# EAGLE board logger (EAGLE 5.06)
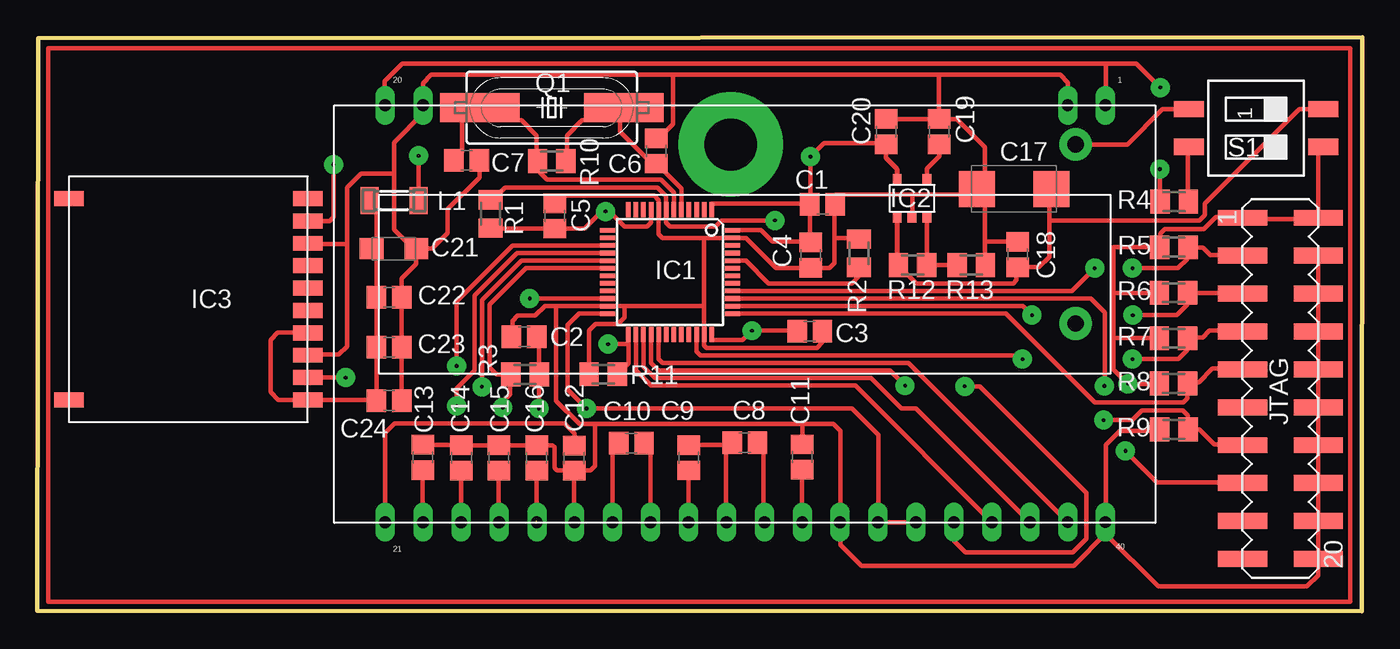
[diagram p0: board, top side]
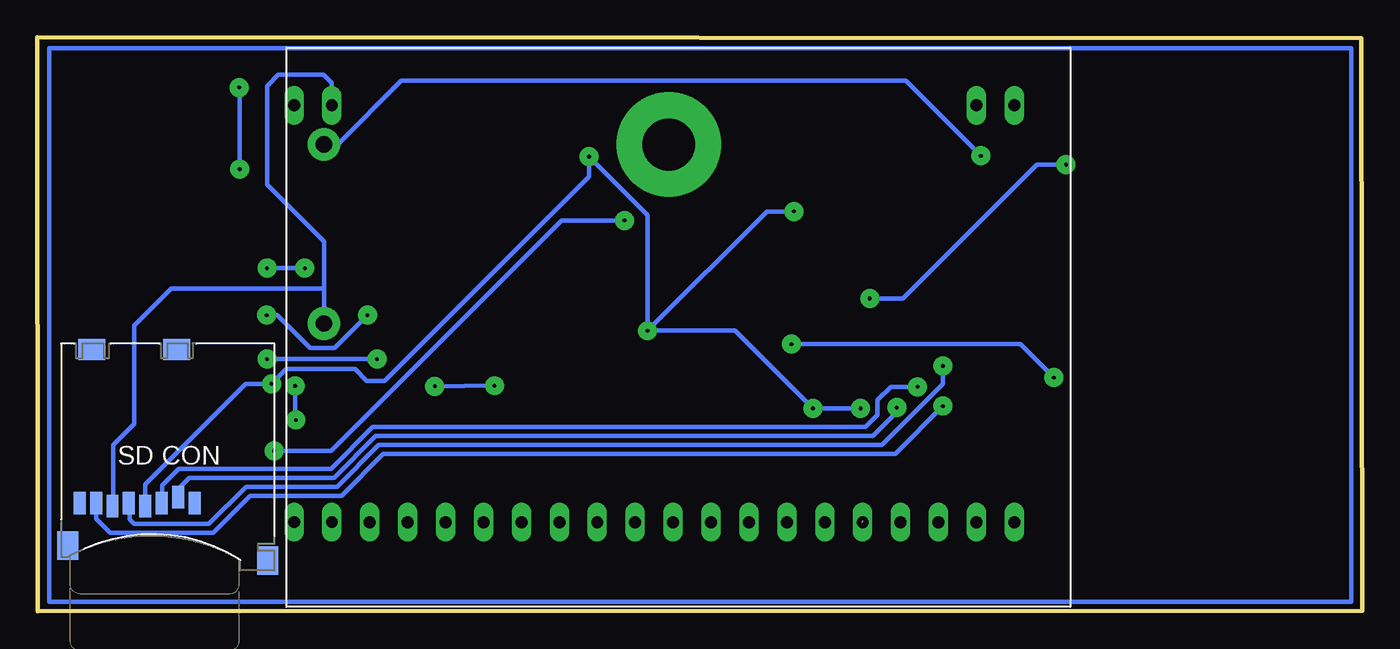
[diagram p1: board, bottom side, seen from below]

Size 88.76 x 38.47 mm. Coordinates in mm from the lower left corner, seen from the top.
Outline: 0,0.03 88.73,0 88.76,38.47 0.05,38.42 0,0.03
Copper layers (1*16): Top 0.035mm / dielectric 1.5mm / Bottom 0.035mm
Design rules "default": minimum track width 10mil, minimum drill 24mil, track to track 8mil, track to pad 8mil, pad to pad 8mil, via to via 8mil, smd to smd 8mil, copper to edge 40mil, drill to drill 8mil, minimum pad ring 10mil, minimum via ring 8mil, stop-mask expansion 4mil, vias tented up to drill 0mil, thermal gap 10mil

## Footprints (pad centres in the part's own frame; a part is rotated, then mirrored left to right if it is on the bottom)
C0805 = smd 1.3 x 1.5: 1 -0.85,0; 2 0.85,0
SMC_C = smd 2.4 x 2.4: + -2.5,0; - 2.5,0
SMC_A = smd 1.6 x 1.4: + -1.5,0; - 1.5,0
SM-1206 = smd 1.2 x 1.8: 1 -1.65,0; 2 1.65,0
HC49UP = smd 5.334 x 1.93: 1 -4.826,0; 2 4.826,0
M0805 = smd 1.3 x 1.6: 1 -0.95,0; 2 0.95,0
SMS-002 = smd 1.092 x 2.007: 1 -1.27,-4.496; 2 1.27,-4.496; 3 1.27,4.496; 4 -1.27,4.496
MA10-2 = smd 1.067 x 3.302: 1 -11.43,-2.54; 2 -11.43,2.54; 3 -8.89,-2.54; 4 -8.89,2.54; 5 -6.35,-2.54; 6 -6.35,2.54; 7 -3.81,-2.54; 8 -3.81,2.54; 9 -1.27,-2.54; 10 -1.27,2.54; 11 1.27,-2.54; 12 1.27,2.54; 13 3.81,-2.54; 14 3.81,2.54; 15 6.35,-2.54; 16 6.35,2.54; 17 8.89,-2.54; 18 8.89,2.54; 19 11.43,-2.54; 20 11.43,2.54
TQFP48 = smd 1.016 x 0.305: 1 -4.191,2.794; 2 -4.191,2.286; 3 -4.191,1.778; 4 -4.191,1.27; 5 -4.191,0.762; 6 -4.191,0.254; 7 -4.191,-0.254; 8 -4.191,-0.762; 9 -4.191,-1.27; 10 -4.191,-1.778; 11 -4.191,-2.286; 12 -4.191,-2.794; 25 4.191,-2.794; 26 4.191,-2.286; 27 4.191,-1.778; 28 4.191,-1.27; 29 4.191,-0.762; 30 4.191,-0.254; 31 4.191,0.254; 32 4.191,0.762; 33 4.191,1.27; 34 4.191,1.778; 35 4.191,2.286; 36 4.191,2.794 | smd 0.305 x 1.016: 13 -2.794,-4.191; 14 -2.286,-4.191; 15 -1.778,-4.191; 16 -1.27,-4.191; 17 -0.762,-4.191; 18 -0.254,-4.191; 19 0.254,-4.191; 20 0.762,-4.191; 21 1.27,-4.191; 22 1.778,-4.191; 23 2.286,-4.191; 24 2.794,-4.191; 37 2.794,4.191; 38 2.286,4.191; 39 1.778,4.191; 40 1.27,4.191; 41 0.762,4.191; 42 0.254,4.191; 43 -0.254,4.191; 44 -0.762,4.191; 45 -1.27,4.191; 46 -1.778,4.191; 47 -2.286,4.191; 48 -2.794,4.191
MICROSD = smd 0.8 x 1.5: 1 -1.94,2.7; 2 -0.84,2.3; 3 0.26,2.7; 4 1.36,2.9; 5 2.46,2.7; 6 3.56,2.9; 7 4.66,2.7; 8 5.76,2.7 | smd 1.4 x 1.9: NC -6.85,6.55; NC3 6.55,5.55 | smd 1.8 x 1.4: NC1 -0.75,-7.6; NC2 4.95,-7.6
GPS_FGMMOPA6B = smd 2 x 1: 1 -2.5,7.5; 2 -2.5,6; 3 -2.5,4.5; 4 -2.5,3; 5 -2.5,1.5; 6 -2.5,0; 7 -2.5,-1.5; 8 -2.5,-3; 9 -2.5,-4.5; 10 -2.5,-6; P$11 13.5,7.5; P$12 13.5,-6
3V110R = drill 1.1 pad 2.184 round: MINUS -2.5,-19; PLUS -2.5,-31 | drill 3.5 pad 7 round: P$1 -25.6,-30.99
LP3985 = smd 0.65 x 0.6: 1 -1.2,0.53; 2 -1.2,-0.47; 3 -1.2,-1.47; 4 1.4,-1.47; 5 1.4,0.53
E_DOG-M_DISPLAY = drill 0.8 long: 1 3.334,0; 2 5.874,0; 19 49.054,0; 20 51.594,0; 21 51.594,27.94; 22 49.054,27.94; 23 46.514,27.94; 24 43.974,27.94; 25 41.434,27.94; 26 38.894,27.94; 27 36.354,27.94; 28 33.814,27.94; 29 31.274,27.94; 30 28.734,27.94; 31 26.194,27.94; 32 23.654,27.94; 33 21.114,27.94; 34 18.574,27.94; 35 16.034,27.94; 36 13.494,27.94; 37 10.954,27.94; 38 8.414,27.94; 39 5.874,27.94; 40 3.334,27.94

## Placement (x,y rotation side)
C1  100nF  [C0805]  52.61,27.28 180 top
C2  100nF  [C0805]  32.62,18.41 0 top
C3  100nF  [C0805]  51.75,18.78 180 top
C4  100nF  [C0805]  51.82,23.87 270 top
C5  100nF  [C0805]  34.66,26.5 90 top
C6  22pF  [C0805]  41.47,30.86 270 top
C7  22pF  [C0805]  28.76,30.21 180 top
C8  1uF  [C0805]  47.4,11.31 180 top
C9  1uF  [C0805]  43.63,10.29 270 top
C10  1uF  [C0805]  39.8,11.26 0 top
C11  1uF  [C0805]  51.24,10.34 90 top
C12  1uF  [C0805]  35.96,10.27 270 top
C13  1uF  [C0805]  25.82,10.31 90 top
C14  1uF  [C0805]  28.42,10.29 90 top
C15  1uF  [C0805]  30.91,10.29 90 top
C16  1uF  [C0805]  33.45,10.29 90 top
C17  100uF  [SMC_C]  65.44,28.31 180 top
C18  1uF  [C0805]  65.68,23.92 90 top
C19  10nF  [C0805]  60.42,32.14 90 top
C20  1uF  [C0805]  56.87,32.14 90 top
C21  10uF  [SMC_A]  23.89,24.31 0 top
C22  1uF  [C0805]  23.57,21.05 0 top
C23  100nF  [C0805]  23.57,17.69 0 top
C24  10nF  [C0805]  23.57,14.13 0 top
L1  [SM-1206]  23.91,27.54 180 top
Q1  8.00MHz  [HC49UP]  34.47,33.76 0 top
R1  10k  [M0805]  30.36,26.64 270 top
R2  10k  [M0805]  55.06,24 270 top
R3  4k7  [M0805]  32.67,15.88 0 top
R4  100  [M0805]  76.16,27.46 0 top
R5  10k  [M0805]  76.15,24.4 180 top
R6  10k  [M0805]  76.12,21.35 180 top
R7  10k  [M0805]  76.12,18.3 180 top
R8  10k  [M0805]  76.12,15.28 180 top
R9  10k  [M0805]  76.14,12.2 0 top
R10  1M  [M0805]  34.46,30.18 0 top
R11  10k  [M0805]  37.92,15.89 180 top
R12  14,3k  [M0805]  58.64,23.2 180 top
R13  10k  [M0805]  62.56,23.2 180 top
S1  SWS002  [SMS-002]  81.65,32.39 270 top
SV1  [MA10-2]  83.28,14.94 270 top
U$1  STM32  [TQFP48]  42.39,22.74 270 top
U$2  MICROSD  [MICROSD]  80.17,9.95 180 bottom
U$3  GPS_FGMMOPA6B  [GPS_FGMMOPA6B]  15.62,21.66 180 top
U$4  3V110R  [3V110R]  72.06,0.29 180 bottom
U$5  LP3985  [LP3985]  58.14,27.57 90 top
U$6  EA_DOG-M_DISPLAY  [E_DOG-M_DISPLAY]  74.9,33.92 180 top

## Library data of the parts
C1-C24 R1-R13 = rcl
L1 = inductor-neosid
Q1 = crystal
S1 = smd-special
SV1 = goldpiny_smd
U$1 = stm32
U$2 = microsd
U$3 = GPS_FGMMOPA6B
U$4 = battery_pack
U$5 = lp3985
U$6 = display_ea_dogm132

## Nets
+3V3: C1.2 C2.2 C3.2 C4.1 C5.1 C20.1 R1.2 R3.2 R5.2 R6.2 R7.2 R8.2 S1.3 SV1.1 SV1.2 U$1.1 U$1.9 U$1.24 U$1.36 U$1.48 U$2.4 U$5.5 U$6.34 U$6.35
BOOT_0: R2.2 U$1.44
GND: C1.1 C2.1 C3.1 C4.2 C5.2 C6.1 C7.1 C11.2 C12.2 C13.2 C14.2 C15.2 C16.2 C17.- C18.2 C19.2 C20.2 C21.- C22.2 C23.2 C24.2 R2.1 R9.1 R11.2 R13.1 SV1.4 SV1.6 SV1.8 SV1.10 SV1.12 SV1.14 SV1.16 SV1.18 SV1.20 U$1.8 U$1.23 U$1.35 U$1.47 U$2.6 U$3.3 U$3.8 U$4.MINUS U$5.2 U$6.2 U$6.19 U$6.26 U$6.33 U$6.40
GPS_DATA: U$1.22 U$3.9
GPS_ENABLE: C21.+ C22.1 C23.1 C24.1 L1.2 U$3.1 U$3.4
JTAG_RST: R1.1 SV1.15 U$1.7
JTAG_TCK: R8.1 SV1.9 U$1.37
JTAG_TDI: R6.1 SV1.5 U$1.38
JTAG_TMS: R7.1 SV1.7 U$1.34
JTAG_TRST: R5.1 SV1.3 U$1.40
KTAG_TDO: R9.2 SV1.13 U$1.39
LCD_A0: U$1.27 U$6.38
LCD_RST: U$1.29 U$6.39
LCD_SCL: U$1.26 U$6.37
LCD_SI: U$1.28 U$6.36
N$2: C19.1 U$5.4
N$3: C7.2 Q1.1 R10.1 U$1.6
N$4: C6.2 Q1.2 R10.2 U$1.5
N$6: L1.1 S1.1 U$4.PLUS
N$7: R12.1 R13.2 U$5.3
N$9: R11.1 U$1.25 U$3.2
N$10: R4.1 U$6.1 U$6.20
N$12: C8.1 U$6.31
N$13: C14.1 U$6.23
N$14: C13.1 U$6.22
N$15: C12.1 U$6.21
N$16: C15.1 U$6.24
N$17: C16.1 U$6.25
N$18: C10.1 U$6.27
N$19: C8.2 C9.1 U$6.30
N$20: C9.2 U$6.29
N$21: C10.2 U$6.28
N$22: C11.1 U$6.32
N$28: R4.2 S1.2
N$36: C17.+ C18.1 R12.2 S1.4 U$5.1
SD_CARD_CLK: U$1.15 U$2.5
SD_CARD_CS: R3.1 U$1.18 U$2.2
SD_CARD_DI: U$1.17 U$2.3
SD_CARD_DO: U$1.16 U$2.7

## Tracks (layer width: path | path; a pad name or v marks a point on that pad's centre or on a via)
+3V3  (via drill 0.25 pad 1.27)
  Top 0.305: S1.3 85.42,31.08 | 75.2,24.32 R5.2 | R5.2 75.18,24.42 72.11,24.42 | 72.11,23.86 72.11,23.94 | R6.2 72.11,21.35 | 75.23,15.25 75.2,15.28 R8.2 75.15,15.26 | 75.15,15.26 75.15,15.12 | 75.15,18.29 R7.2 75.15,18.32 72.11,18.32 | 75.15,15.26 75.14,15.25 v73.07,15.25 | v73.07,15.25 72.11,16.21 72.11,16.39 | 72.11,16.39 72.11,18.32 | U$1.36 45.18,18.17 47.24,18.17 v47.87,18.81 50.87,18.81 | 50.77,18.42 50.77,18.68 50.8,18.68 C3.2 50.87,18.81 | 50.52,13.6 v36.8,13.6 35.53,14.87 35.53,19.19 36.29,19.95 U$1.24 | 50.52,13.6 50.77,13.6 | 51.81,26.68 51.72,26.68 C1.2 | 58.9,5.98 U$6.35 U$6.34 56.36,6.01 56.36,11.82 54.58,13.6 50.52,13.6 | 58.9,5.98 | 80.82,26.3 SV1.1 | 80.82,26.3 80.15,26.3 80.02,26.43 78.96,26.43 78.16,25.63 75.54,25.63 75.23,25.32 75.23,24.43 R5.2 | 85.19,26.3 85.06,26.43 | 80.82,26.3 85.19,26.3 | 85.82,26.3 SV1.2 | 85.82,31.12 S1.3 | 85.19,26.3 85.82,26.3 | S1.3 85.9,30.87 85.82,30.87 85.82,26.3 | 72.11,24.42 72.11,23.86 | 72.11,23.86 72.11,21.35 | 72.11,18.32 72.11,21.35 | C1.2 51.71,26.67 51.76,26.61 51.76,24.77 | U$1.9 41.12,26.04 40.86,25.79 39.34,25.79 38.32,26.81 v38.07,26.81 37.82,26.81 36.66,25.65 C5.1 30.37,25.65 30.34,25.69 R1.2 | 50.87,18.81 v47.88,18.81 | v33.6,13.6 33.6,15.6 R3.2 33.62,18.41 C2.2 | C1.2 51.73,27.31 45.18,27.31 U$1.1 | U$1.48 48.48,25.54 49.25,24.77 51.76,24.77 | 51.76,24.77 C4.1 | 56.87,31.12 C20.1 | U$5.5 57.61,29.42 | U$5.5 57.61,29.67 56.87,30.41 56.87,31.12 | 56.87,31.12 56.87,31.38 52.8,31.38 | C1.2 51.79,27.3 51.79,30.36 v51.79,30.47 52.7,31.38 52.8,31.38 | U$5.5 57.63,28.99 57.63,29.6 56.87,30.36 56.87,31.12 | 56.87,31.12 56.61,31.38 52.8,31.38 | 72.11,16.39 72.11,24.42
  Top 0.305: 72.11,16.39 72.11,16.22 v73.07,15.25
  Bottom 0.305: v33.6,13.6 v36.8,13.6 42.01,18.81 v47.87,18.81 | v47.87,18.81 47.85,18.81 | v47.87,18.81 47.03,18.81 | v38.07,26.81 39.87,26.81 v47.87,18.81 | v47.87,18.81 47.87,26.55 v51.79,30.47 51.79,29.14 65.48,15.45 66.68,15.45 67.48,16.25 72.07,16.25 v73.07,15.25 74.78,15.25 81.53,8.51 U$2.4
BOOT_0
  Top 0.305: U$1.44 47.47,23.5 48.99,21.98 54.58,21.98 55.09,22.49 55.09,23.02 R2.2
GND
  Top 0.305: C12.2 35.96,9.34 35.96,6.49 | 35.96,6.49 35.96,6.07 | C13.2 | C13.2 28.42,11.16 C14.2 30.85,11.14 30.86,11.13 30.86,11.14 C15.2 33.34,11.14 33.35,11.13 33.35,11.14 C16.2 34.51,11.14 34.64,11.01 34.64,9.61 34.82,9.43 35.94,9.43 C12.2 | 35.58,9.41 35.59,9.42 C12.2 | 51.22,11.21 51.2,11.21 | 51.22,11.21 C11.2 | C12.2 35.96,9.46 36.06,9.46 37.05,9.46 37.36,9.76 37.36,12.56 | U$3.8 18.17,24.62 20.13,24.62 | 20.13,24.62 20.24,24.62 | U$3.3 18.11,17.18 18.11,17.2 20.18,17.2 20.74,17.76 20.74,24.62 | 25.88,33.97 25.88,33.92 U$6.19 | 20.74,24.62 20.13,24.62 | 34.77,20.46 U$1.23 | C1.1 53.41,26.65 53.41,25.03 | 53.36,26.7 53.36,26.69 C1.1 | 39.34,20.46 34.77,20.46 | 44.67,20.46 39.34,20.46 | 44.93,25.03 44.67,25.03 44.67,20.46 | 44.93,25.03 U$1.47 47.47,25.03 49.47,23.02 C4.2 53.08,23.02 53.41,23.35 53.41,25.03 | 41.63,27.06 U$1.8 | C3.1 52.6,18.04 52.22,17.66 44.83,17.66 44.67,17.81 U$1.35 44.67,20.46 | 41.63,27.06 41.63,25.28 41.88,25.03 44.93,25.03 | 69.06,34.02 69.06,33.92 U$6.2 69.06,33.95 69.06,35.44 68.55,35.95 60.41,35.95 | 35.96,6.49 36.04,6.49 36.04,5.98 U$6.26 | 85.82,4.2 SV1.20 | 85.82,4.2 SV1.18 SV1.16 SV1.14 SV1.12 SV1.10 SV1.8 SV1.6 | SV1.6 85.82,21.47 | 85.82,24.01 SV1.4 SV1.6 | 41.63,27.06 41.63,27.57 41.34,27.85 34.97,27.85 34.66,27.54 C5.2 | C24.2 C23.2 | C23.2 | C23.2 C22.2 24.42,22.29 25.39,23.26 C21.- | C21.- 25.67,24.03 25.67,23.8 23.89,25.58 23.89,29.25 | 34.77,20.46 34.01,20.46 33.36,19.81 32.18,19.81 31.84,19.47 31.84,18.48 C2.1 | 37.36,12.56 36.32,12.56 34.77,14.11 34.77,20.46 | 39.34,20.46 39.34,19.69 38.9,19.25 37.38,19.25 36.97,18.83 R11.2 | U$6.19 25.85,33.38 23.89,31.42 23.89,29.25
  Top 0.305: 41.61,31.81 C6.1 41.81,32.15 42.08,32.15 42.58,32.65 42.58,35.95 43.15,35.95 | 37.36,12.56 51.28,12.56 | 51.22,11.21 51.28,11.27 51.28,12.56 | 85.82,4.2 85.82,2.42 85.06,1.66 75.09,1.66 71.57,5.18 | R9.1 75.07,12.07 72.51,12.07 71.6,11.16 71.6,5.5 71.57,5.47 | 51.28,12.56 53.33,12.56 53.82,12.07 53.82,6.01 U$6.33 53.82,5.95 53.82,4.45 55.22,3.05 69.43,3.05 71.57,5.18 | R2.1 54.98,25.03 53.41,25.03 | 71.57,5.18 71.57,5.47 | 71.57,5.47 U$6.40 | U$6.19 25.85,35.41 26.39,35.95 43.15,35.95 | 43.15,35.95 60.41,35.95 | 53.46,27.92 C1.1 | 59.91,32.99 C19.2 | U$5.2 58.64,26.41 58.64,27.92 | 53.46,27.92 58.29,27.92 | 59.91,32.99 60.33,32.99 arc-90 60.42,32.9 60.41,32.9 60.41,35.95 | 59.91,32.99 C20.2 | 58.64,27.92 53.46,27.92 | 58.64,27.92 62.55,27.92 C17.- 62.94,27.82 63.47,27.82 63.47,24.77 | R13.1 63.47,23.2 63.47,24.77 | C18.2 63.47,24.77 | 63.47,24.77 63.47,31.12 61.6,32.99 59.91,32.99 | C7.1 29.61,29.08 27.48,26.95 27.48,25.35 26.44,24.31 C21.- | 20.74,24.62 20.74,28.41 21.68,29.35 23.79,29.35 23.89,29.25
  Bottom 0.305: U$6.2 69.03,34.39 69.06,34.43 69.06,35.44 69.57,35.95 72.61,35.95 73.38,35.19 73.38,28.58 69.56,24.77 69.56,21.65 | 69.56,21.65 U$4.MINUS | U$2.6 83.68,7.09 83.68,11.15 82.28,12.55 82.28,19.15 79.78,21.65 69.56,21.65
GPS_DATA  (via drill 0.25 pad 1.27)
  Top 0.305: 18.15,26.14 U$3.9 18.14,26.15 19.58,26.15 19.84,26.41 v19.84,29.94 | v32.99,20.96 U$1.22
  Bottom 0.305: v32.99,20.96 30.77,20.96 21.79,29.94 v19.84,29.94
GPS_ENABLE
  Top 0.305: U$3.4 18.12,18.67 16.1,18.67 15.62,18.19 15.62,14.71 16.15,14.18 18.13,14.18 18.13,14.17 U$3.1 18.14,14.15 22.69,14.15 C24.1 C23.1 22.72,21.35 C22.1 22.72,23.98 C21.+ 22.74,24.65 22.74,27.07 22.27,27.54 L1.2
JTAG_RST  (via drill 0.25 pad 1.27)
  Top 0.305: 80.49,8.52 80.15,8.52 80.02,8.65 75,8.65 v72.9,10.75 | 80.49,8.52 80.67,8.52 SV1.15 | 80.49,8.52 81.5,8.52 | R1.1 30.76,28 30.95,28 31.35,28.4 41.56,28.4 42.13,27.82 U$1.7 42.13,26.04 42.39,25.79 45.44,25.79 45.84,26.2 v49.42,26.2
  Bottom 0.305: v49.42,26.2 53.64,26.2 69.09,10.75 v72.9,10.75
JTAG_TCK
  Top 0.305: R8.1 77.14,15.35 77.82,15.35 78.73,16.27 80.02,16.27 80.15,16.14 80.82,16.14 | R8.1 77.08,15.27 | R8.1 77.07,15.16 77.06,15.15 77.06,14.28 76.78,14 70.84,14 64.89,19.95 U$1.37 | 80.82,16.14 81,16.14 | 80.82,16.14 SV1.9
JTAG_TDI  (via drill 0.25 pad 1.27)
  Top 0.305: R6.1 77.06,21.35 | R6.1 | R6.1 80.02,21.35 80.15,21.22 80.82,21.22 | R6.1 77.06,21.34 77.06,20.56 76.35,19.85 v73.4,19.85 | 80.82,21.22 81,21.22 | 80.82,21.22 SV1.5 | v66.65,19.85 66.04,20.46 U$1.38
  Bottom 0.305: v66.65,19.85 68.83,17.66 70.5,17.66 72.68,19.85 v73.4,19.85
JTAG_TMS  (via drill 0.25 pad 1.27)
  Top 0.305: 77.06,18.35 77.06,18.31 R7.1 | 77.06,18.35 78.07,18.35 78.53,18.81 80.02,18.81 80.15,18.68 80.74,18.68 | 77.06,18.35 77.06,17.51 76.45,16.9 v73.38,16.9 | U$1.34 44.17,17.41 44.42,17.15 65.76,17.15 v66.01,16.9 | 80.74,18.68 SV1.7 | 80.74,18.68 81.25,18.68
  Bottom 0.305: v66.01,16.9 v73.38,16.9
JTAG_TRST  (via drill 0.25 pad 1.27)
  Top 0.305: R5.1 77.03,24.39 77.03,23.61 76.42,23 v73.38,23 | R5.1 | R5.1 78.07,24.39 78.58,23.89 80.02,23.89 80.15,23.76 80.74,23.76 SV1.3 | 46.45,21.47 U$1.40 69.31,21.47 v70.84,23
  Bottom 0.305: v70.84,23 v73.38,23
KTAG_TDO  (via drill 0.25 pad 1.27)
  Top 0.305: 77.08,12.18 77.08,12.19 R9.2 | 77.08,12.18 77.85,12.18 78.84,11.19 80.02,11.19 80.15,11.06 80.82,11.06 | 46.45,20.96 U$1.39 62.2,20.96 | 62.2,20.96 64.74,20.96 | 77.08,12.18 77.08,13.12 76.75,13.45 73.99,13.45 73.35,12.81 v71.43,12.81 | 80.82,11.06 81,11.06 | 80.82,11.06 SV1.13 | 62.2,20.96 70.58,20.96 71.51,20.04 71.51,14.97 arc-90 v71.49,15.11
  Bottom 0.305: v71.49,15.11 71.49,12.84 v71.43,12.81
LCD_A0
  Top 0.305: U$1.27 40.61,16.39 41.37,15.63 55.85,15.63 57.88,13.6 58.87,13.6 U$6.38 66.52,5.98
LCD_RST
  Top 0.305: 69.02,6.02 69.06,5.98 U$6.39 58.36,16.65 42.64,16.65 | 42.64,16.65 42.39,16.65 | U$1.29 41.63,16.9 41.88,16.65 42.64,16.65
LCD_SCL
  Top 0.305: U$1.26 40.1,16.14 41.12,15.12 54.8,15.12 U$6.37 | U$6.37 63.98,5.98 | U$6.37
LCD_SI  (via drill 0.25 pad 1.27)
  Top 0.305: U$1.28 41.12,16.65 41.63,16.14 57.12,16.14 v58.14,15.12 | U$6.36 61.44,5.98 | U$6.36 | U$6.36 61.41,6.01 | v62.14,15.08 63.15,15.08 70.28,7.95 70.28,4.85 69.38,3.95 62.18,3.95 61.41,4.73 U$6.36
  Bottom 0.305: v58.14,15.12 v62.14,15.08
N$1
  Top 0.305: 0.73,0.64 0.73,37.73 87.96,37.73 87.96,0.64 0.73,0.64
N$2
  Top 0.305: C19.1 60.42,30.5 59.61,29.68 U$5.4
N$3
  Top 0.305: C7.2 28.46,30.76 28.46,33.27 28.94,33.76 Q1.1 30.57,33.76 31.42,32.9 32.44,32.9 33.45,31.89 33.45,30.24 R10.1 | U$1.6 42.64,28.08 41.78,28.94 34.16,28.94 33.51,29.59 R10.1 | R10.1 33.45,30.12
N$4
  Top 0.305: R10.2 35.48,30.25 35.48,31.89 36.5,32.9 37.26,32.9 38.11,33.76 Q1.2 39.04,33.5 39.04,32.14 41.07,30.11 C6.2 | C6.2 41.47,29.71 | U$1.5 43.15,28.33 C6.2
N$5
  Bottom 0.305: 0.73,0.64 0.73,37.73 87.96,37.73 87.96,0.64 0.73,0.64
N$6  (via drill 0.25 pad 1.27)  (1 unrouted)
  Top 0.305: 76.68,33.66 76.4,33.66 S1.1 77.17,33.64 | 77.17,33.64 77.29,33.64 | 77.17,33.64 75.38,33.64 73.03,31.29 U$4.PLUS | 25.56,28.25 L1.1 25.56,30.55
  Bottom 0.305: v25.54,30.53 30.56,35.55 64.37,35.55 68.64,31.29 U$4.PLUS
N$7
  Top 0.305: U$5.3 59.61,23.22 arc-90 R12.1 R13.2 arc-90 R13.2
N$9  (via drill 0.25 pad 1.27)
  Top 0.305: v20.65,15.66 20.25,15.66 U$3.2 | 39.59,17.95 39.59,16.62 R11.1 | 39.59,17.95 U$1.25 | v38.24,17.91 39.55,17.91 39.59,17.95
  Bottom 0.305: v38.24,17.91 22.9,17.91 v20.65,15.66
N$10  (via drill 0.25 pad 1.27)
  Top 0.305: 75.22,27.57 R4.1 75.2,27.55 v75.2,29.64 | 23.34,34.02 23.34,33.92 U$6.20 | 23.34,34.02 23.29,34.02 23.29,34.81 23.26,34.83 23.26,35.52 24.46,36.71 71.6,36.71 | 23.34,34.02 23.34,34.17 | U$6.1 71.6,33.92 71.6,33.99 | 71.6,33.99 71.55,33.99 | 71.6,36.71 71.6,33.99 | 71.6,36.71 73.63,36.71 | 73.63,36.71 | 73.63,36.71 v75.24,35.1
  Bottom 0.305: v75.24,35.1 75.2,35.1 v75.2,29.64
N$12
  Top 0.305: C8.1 48.66,10.9 48.66,6.11 48.74,6.11 48.74,5.98 U$6.31
N$13
  Top 0.305: C14.1 28.39,9.41 28.39,6.23 | 28.39,6.23 28.39,5.9 | 28.39,6.23 28.42,6.23 28.42,5.98 U$6.23
N$14
  Top 0.305: C13.1 25.83,6.49 | 25.83,6.49 25.83,6.05 | 25.83,6.49 25.88,6.49 25.88,5.98 U$6.22
N$15
  Top 0.305: 35.96,11.69 C12.1 35.99,11.14 35.99,11.92 35.33,12.58 24.86,12.58 | 24.86,12.58 24.35,12.58 | 23.29,6.49 23.29,6.08 | 23.29,6.49 23.29,11.95 23.92,12.58 24.86,12.58 | 23.29,6.49 23.34,6.49 23.34,5.98 U$6.21
N$16
  Top 0.305: C15.1 30.91,9.41 30.91,5.78 30.96,5.78 30.96,5.98 | 30.96,5.98 | U$6.24 30.96,5.98 | 30.96,5.98 30.96,6.49
N$17  (1 unrouted)
  Top 0.305: C16.1 33.45,6.49 33.45,6.07
N$18
  Top 0.305: C10.1 38.53,11.26 38.53,6.23 | 38.53,6.23 38.53,6.07 | 38.53,6.23 38.32,6.23 38.32,5.98 U$6.27
N$19
  Top 0.305: 46.12,10.88 C8.2 | 46.12,10.88 46.12,5.85 46.2,5.85 | C9.1 43.63,11.16 46.12,11.16 46.12,10.88 | 46.2,5.85 46.2,5.72 | U$6.30 46.2,5.98 46.2,5.85
N$20
  Top 0.305: C9.2 U$6.29 43.66,5.98 | 43.66,5.98 43.66,5.72 | U$6.29 43.66,5.98 | 43.66,5.98
N$21
  Top 0.305: C10.2 41.07,11.26 41.07,6.23 | 41.07,6.23 41.07,6.07 | 41.07,6.23 41.12,6.23 41.12,5.98 U$6.28
N$22
  Top 0.305: C11.1 51.23,9.47 51.23,6.23 | 51.23,6.23 51.23,6.08 | 51.23,6.23 51.28,6.23 51.28,5.98 U$6.32
N$28
  Top 0.305: R4.2 77.13,27.56 77.08,27.61 77.08,31.05 S1.2 76.4,31.12 76.42,31.12
N$36
  Top 0.305: 86.13,33.61 86.13,33.64 S1.4 85.39,33.67 84.55,33.67 78.2,27.31 78.2,26.55 77.84,26.19 67.79,26.19 67.79,25.54 | U$5.1 | U$5.1 57.61,23.29 arc90 R12.2 | U$5.1 57.61,23.27 arc90 57.63,23.25 58.9,21.98 65.38,21.98 65.6,22.21 65.6,22.99 C18.1 67.1,23.07 67.79,23.76 67.79,25.54 | 67.79,25.54 67.79,28.16 C17.+
SD_CARD_CLK  (via drill 0.25 pad 1.27)
  Top 0.305: 38.32,24.52 U$1.15 31.85,24.52 28.08,20.75 v28.08,16.45
  Bottom 0.305: U$2.5 82.58,7.21 82.58,6.15 82.28,5.85 77.28,5.85 74.78,8.35 68.68,8.35 65.88,11.15 32.18,11.15 28.08,15.25 v28.08,16.45
SD_CARD_CS  (via drill 0.25 pad 1.27)
  Top 0.305: 38.32,23 U$1.18 32.73,23 30.28,20.55 30.28,16.35 30.76,15.88 R3.1 31.68,15.84 31.68,14.55 31.18,14.05 v31.18,13.65
  Bottom 0.305: U$2.2 79.28,7.69 79.28,8.25 78.58,8.95 68.88,8.95 66.08,11.75 32.78,11.75 31.18,13.35 v31.18,13.65
SD_CARD_DI  (via drill 0.25 pad 1.27)
  Top 0.305: U$1.17 32.44,23.5 29.78,20.85 v29.78,15.05
  Bottom 0.305: U$2.3 80.38,7.29 80.38,8.45 79.28,9.55 69.58,9.55 | 69.58,9.55 69.48,9.55 | 69.58,9.55 69.08,9.55 66.28,12.35 33.28,12.35 32.48,13.15 32.48,14.15 31.58,15.05 v29.78,15.05
SD_CARD_DO  (via drill 0.25 pad 1.27)
  Top 0.305: U$1.16 32.15,24.01 29.28,21.15 29.28,16.15 28.08,14.95 v28.08,13.75
  Bottom 0.305: U$2.7 84.83,6.19 83.88,5.25 76.98,5.25 74.48,7.75 68.38,7.75 65.58,10.55 31.28,10.55 v28.08,13.75

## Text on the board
tPlace: JTAG
bPlace: SD CON
tNames: IC2 | IC1 | IC3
